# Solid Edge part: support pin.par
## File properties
Author: Sarvanan
Template: sync ansi part.par
Last saved by: TIET
Revision: 11
Application: Solid Edge
Accuracy: 0.990
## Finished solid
Body 1: solid body, 9 faces, 8 edges, 0 vertices.
  Faces by surface: plane 4, cylinder 3, cone 2
  Edges by curve: circle 8
Bounding box of the edges (mm): 6.350 x 6.350 x 66.675, from (12.0753, 27.1097, -66.675) to (18.4253, 33.4597, 0).
Cylindrical faces by radius (mm): R2.413 x2, R3.175 x1
Conical faces (half-angle, radius in mm at the cone's reference point): 44.9733 deg R1.6517 x2
Planar faces by outward normal: +z 2, -z 2
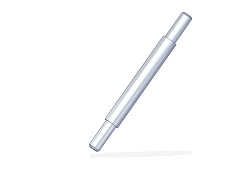
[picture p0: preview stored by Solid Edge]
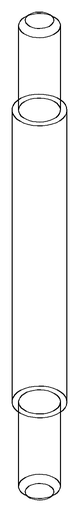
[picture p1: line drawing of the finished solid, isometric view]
